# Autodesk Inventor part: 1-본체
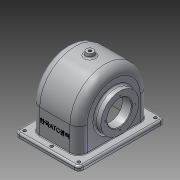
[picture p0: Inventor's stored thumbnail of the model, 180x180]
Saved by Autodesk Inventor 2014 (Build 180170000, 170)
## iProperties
Created: 2015-09
Part Number: 1-본체
Material: 알루미늄 6061
Document SubType Name: Modeling
Designer: Administrator
Density: 2.71 g/cm^3
Appearance: 알루미늄 - 평지
Mass: 722.8 g
Surface Area: 892.269 cm^2
Volume: 266.716 cm^3
Author: Administrator
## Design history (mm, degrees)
sketch "스케치1"
  geometry: L1 (-70, 0)-(70, 0); L2 (70, 0)-(70, -7); L3 (70, -7)-(-70, -7); L4 (-70, -7)-(-70, 0); L5 (-57, 40)-(-57, 0); L6 (57, 40)-(57, 0); L7 (0, 97)-(0, -7); A1 r 57 centre (0, 40) between (40.608, 0) and (-40.608, 0); 1 further point
  constraints: 14 end point, 5 point on circle, 4 point on line, 3 parallel, 2 midpoint, 2 perpendicular, 2 tangent, 1 centre point, 1 horizontal, 1 vertical, 1 vertical alignment
  dimensions: "d1" = 140 distance of L2.end L3.end; "d2" = 7 distance of L1.end L2.end; "d6" = 114 diameter of A1; "d7" = 104 distance of L7.start L7.end
extrude "돌출1" new body sketch "스케치1" stored distance "d8" = 77; taper "d9" = 0 deg
extrude "돌출2" join sketch "스케치1" stored distance "d10" = 104; taper "d11" = 0 deg
sketch "스케치2"
  geometry: L1 (-51, 40)-(51, 40); L2 (51, 40)-(51, -7); L3 (51, -7)-(-51, -7); L4 (-51, -7)-(-51, 40); L5 (70, -7)-(-70, -7) reference; A1 r 57 centre (0, 40) between (57, 40) and (-57, 40) reference; A2 r 51 centre (0, 40) between (51, 40) and (-51, 40); 1 further point
  constraints: 8 end point, 2 parallel, 2 point on circle, 1 centre point, 1 collinear, 1 horizontal, 1 midpoint, 1 perpendicular
  dimensions: "d12" = 6 radial gap between concentric circles of A1 A2
extrude "돌출3" cut sketch "스케치2" stored distance "d13" = 67; taper "d14" = 0 deg
node "작업 평면1"
sketch "스케치3"
  geometry: C1 r 28 at (40, 0); A1 r 57 centre (40, 0) between (40, -57) and (40, 57) reference; 1 further point
  constraints: 1 centre point, 1 concentric
  dimensions: "d16" = 56 diameter of C1
extrude "돌출4" join sketch "스케치3" stored distance "d17" = 66; taper "d18" = 40 deg
sketch "스케치4"
  geometry: L1 (19.5, 68)-(33.5, 79.747) reference; L2 (19.5, 68)-(19.5, 12) reference; L3 (38.5, 77.416)-(33.237, 73); L4 (35.5, 40)-(38.5, 40); L5 (38.5, 40)-(38.5, 77.416); L6 (33.237, 73)-(35.5, 73); L7 (35.5, 73)-(35.5, 40); L8 (38.5, 40)-(38.5, 97) reference; 2 further points
  constraints: 10 end point, 3 perpendicular, 1 collinear, 1 horizontal alignment, 1 midpoint, 1 parallel
  dimensions: "d19" = 5 distance between parallel lines of L1 L3; "d20" = 16 distance between parallel lines of L2 L7; "d21" = 66 diameter of L3.end L4
revolve "회전1" sketch "스케치4" stored, may be unused: angle "d22" = 90 deg
hole "구멍1" diameter "d25" = 40; stored, may be unused: countersink angle "d29" = 90 deg, drill point angle "d31" = 118 deg; dims "d23" = 10, "d24" = 10, "d26" = 6, "d27" = 4, "d28" = 2, "d30" = 16
chamfer "모따기1" distance "d32" = 1; stored, may be unused: second distance "d33" = 2, angle "d34" = 45 deg
fillet "모깎기1" dims "d35" = 3
sketch "스케치5"
  geometry: L1 (0, 0)-(28, 0); C1 r 33 at (0, 0) reference; 1 further point
  constraints: 2 end point, 1 coincident, 1 horizontal
  dimensions: "d36" = 28 distance of L1.start L1.end
hole "구멍2" sketch "스케치5" at (28, 0) diameter "d37" = 2.459; stored, may be unused: countersink angle "d41" = 90 deg, drill point angle "d43" = 118 deg; dims "d38" = 7, "d39" = 4, "d40" = 2, "d42" = 9
sketch "스케치6"
  geometry: C1 r 31 at (-40, 0); A1 r 57 centre (-40, 0) between (-40, 57) and (-40, -57) reference; 1 further point
  constraints: 1 centre point, 1 concentric
  dimensions: "d47" = 62 diameter of C1
extrude "돌출5" join sketch "스케치6" distance "d48" = 10; taper "d49" = 0 deg
hole "구멍3" diameter "d52" = 40; stored, may be unused: countersink angle "d56" = 90 deg, drill point angle "d58" = 0 deg; dims "d50" = 10, "d51" = 10, "d53" = 7, "d54" = 4, "d55" = 2, "d57" = 9
sketch "스케치7"
  geometry: L1 (0, 0)-(-24, 0); C1 r 31 at (0, 0) reference; 1 further point
  constraints: 2 end point, 1 coincident, 1 horizontal
  dimensions: "d59" = 24 distance of L1.start L1.end
hole "구멍4" sketch "스케치7" at (-24, 0) diameter "d60" = 2.459; stored, may be unused: countersink angle "d64" = 90 deg, drill point angle "d66" = 118 deg; dims "d61" = 6, "d62" = 4, "d63" = 2, "d65" = 8
chamfer "모따기2" distance "d70" = 1; stored, may be unused: second distance "d71" = 2, angle "d72" = 45 deg
fillet "모깎기2" dims "d73" = 9
fillet "모깎기3" dims "d74" = 14
fillet "모깎기4" dims "d75" = 7
node "작업 평면2"
sketch "스케치8"
  geometry: C1 r 6 at (45, -70); 1 further point
  constraints: 1 centre point, 1 coincident
  dimensions: "d77" = 12 diameter of C1
extrude "돌출6" join sketch "스케치8" stored distance "d78" = 10; taper "d79" = 10 deg
fillet "모깎기5" dims "d80" = 3
hole "구멍5" diameter "d83" = 4.459; stored, may be unused: countersink angle "d87" = 90 deg, drill point angle "d89" = 118 deg; dims "d84" = 20, "d85" = 4, "d86" = 2, "d88" = 8, "d90" = 10, "d91" = 10
sketch "스케치9"
  geometry: L1 (89, 132)-(45, 132); L2 (45, 132)-(45, 8); L3 (45, 8)-(89, 8); L4 (89, 8)-(89, 132); L5 (45, 132)-(1, 132); L6 (1, 132)-(1, 8); L7 (1, 8)-(45, 8); L8 (45, 8)-(45, 132); 2 further points
  constraints: 16 end point, 4 parallel, 2 horizontal, 2 midpoint, 2 perpendicular, 1 collinear, 1 horizontal alignment
  dimensions: "d92" = 124 distance between parallel lines of L3 L1; "d93" = 44 distance of L1.start L1.end; "d94" = 44 distance of L1.end L5.end
hole "구멍6" sketch "스케치9" at (89, 132) diameter "d95" = 5; stored, may be unused: countersink angle "d99" = 90 deg, drill point angle "d101" = 118 deg; dims "d96" = 6, "d97" = 4, "d98" = 2, "d100" = 8
fillet "모깎기6" dims "d108" = 3
fillet "모깎기7" dims "d109" = 1
sketch "스케치10"
  geometry: L1 (-0.283, -13.398)-(49.283, -13.398); L2 (49.283, -13.398)-(49.283, -20.602); L3 (49.283, -20.602)-(-0.283, -20.602); L4 (-0.283, -20.602)-(-0.283, -13.398); L5 (-20.5, -47)-(69.5, -47) reference; L6 (-14, 0)-(-14, -39) reference; 3 further points
  constraints: 2 midpoint, 2 other
  dimensions: "d110" = 30 distance from line of L5 point (-0.283, -17); "d111" = 38.5 distance from line of L6 point (24.5, -13.398)
feature "엠보싱1" sketch "스케치10" dims "d12" = 6, "d112" = 0.5, "d113" = 0
fillet "모깎기8" dims "d114" = 3
fillet "모깎기9" dims "d115" = 0.5
node "솔리드1"
pattern_circular "원형 패턴1" dims angle "d45" = 360 deg
pattern_circular "원형 패턴2" dims angle "d68" = 360 deg
pattern_linear "직사각형 패턴1" dims "d104" = 44 (= d93), "d107" = 124 (= d92)
other parameters: "d15" = -19
